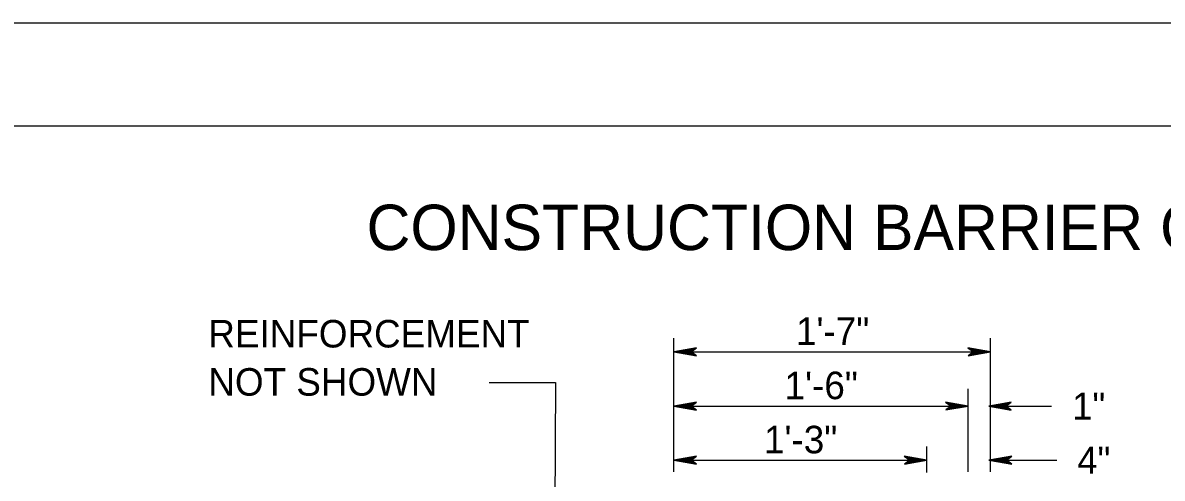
# Model space of a CAD drawing. Extents: x 499866 to 500993, y 499985 to 500645.
# Drawn here: x 500238.9 to 500404.4, y 500578.8 to 500645 of the extents above; entities that cross this region are included whole.
import ezdxf

# ---------------------------------------------------------------- set-up
doc = ezdxf.new("R2010")
doc.units = 0
for name, color, linetype in [('1', 7, 'Continuous'), ('24', 7, 'Continuous'), ('41', 7, 'Continuous'), ('5', 7, 'Continuous')]:
    doc.layers.add(name, color=color, linetype=linetype)

msp = doc.modelspace()

# ---------------------------------------------------------------- linework, layer by layer
at = {"layer": '1'}
for p, q in [((499944.83, 500645), (500993, 500645)), ((500990, 500630), (500000, 500630))]:
    msp.add_line(p, q, dxfattribs=at)
at = {"layer": '24'}
for points in [[(500333.48, 500597.19), (500336.76, 500596.61), (500335.97, 500597.19), (500336.74, 500597.76), (500333.48, 500597.19), (500333.7, 500597.19), (500336.66, 500596.65), (500335.91, 500597.19), (500336.61, 500597.71), (500333.82, 500597.2), (500333.93, 500597.19), (500336.47, 500596.74), (500335.9, 500597.19), (500336.48, 500597.64), (500333.98, 500597.19), (500334.08, 500597.2), (500336.3, 500596.8), (500335.87, 500597.19), (500336.31, 500597.59), (500334.4, 500597.2), (500334.59, 500597.2), (500336.14, 500596.88), (500335.84, 500597.18), (500336.16, 500597.5), (500334.62, 500597.19), (500334.79, 500597.18), (500335.96, 500596.98), (500335.74, 500597.2), (500335.98, 500597.43), (500334.95, 500597.19), (500335.12, 500597.17), (500335.82, 500597.04), (500335.7, 500597.19), (500335.9, 500597.37), (500335.2, 500597.19), (500335.66, 500597.08), (500335.6, 500597.2), (500335.8, 500597.33), (500335.32, 500597.2), (500335.62, 500597.13), (500335.49, 500597.23), (500335.64, 500597.29), (500335.49, 500597.19), (500335.57, 500597.18)], [(500379.45, 500597.19), (500376.17, 500597.77), (500376.96, 500597.19), (500376.19, 500596.62), (500379.45, 500597.19), (500379.23, 500597.18), (500376.26, 500597.72), (500377.02, 500597.18), (500376.32, 500596.66), (500379.11, 500597.17), (500379, 500597.19), (500376.46, 500597.64), (500377.03, 500597.18), (500376.45, 500596.74), (500378.95, 500597.19), (500378.84, 500597.17), (500376.62, 500597.57), (500377.06, 500597.19), (500376.62, 500596.79), (500378.53, 500597.17), (500378.34, 500597.17), (500376.79, 500597.49), (500377.09, 500597.2), (500376.77, 500596.87), (500378.31, 500597.19), (500378.14, 500597.2), (500376.97, 500597.4), (500377.19, 500597.17), (500376.95, 500596.95), (500377.98, 500597.19), (500377.81, 500597.2), (500377.11, 500597.34), (500377.22, 500597.18), (500377.03, 500597), (500377.73, 500597.19), (500377.27, 500597.3), (500377.33, 500597.17), (500377.13, 500597.04), (500377.61, 500597.17), (500377.31, 500597.25), (500377.44, 500597.15), (500377.29, 500597.09), (500377.43, 500597.18), (500377.36, 500597.2)], [(500333.48, 500589.31), (500336.76, 500588.73), (500335.97, 500589.31), (500336.74, 500589.88), (500333.48, 500589.31), (500333.7, 500589.32), (500336.66, 500588.78), (500335.91, 500589.32), (500336.61, 500589.84), (500333.82, 500589.33), (500333.93, 500589.31), (500336.47, 500588.86), (500335.9, 500589.32), (500336.48, 500589.76), (500333.98, 500589.31), (500334.08, 500589.33), (500336.3, 500588.93), (500335.87, 500589.31), (500336.31, 500589.71), (500334.4, 500589.33), (500334.59, 500589.33), (500336.14, 500589.01), (500335.84, 500589.3), (500336.16, 500589.63), (500334.62, 500589.31), (500334.79, 500589.3), (500335.96, 500589.1), (500335.74, 500589.33), (500335.98, 500589.55), (500334.95, 500589.31), (500335.12, 500589.3), (500335.82, 500589.16), (500335.7, 500589.32), (500335.9, 500589.49), (500335.2, 500589.31), (500335.66, 500589.2), (500335.6, 500589.33), (500335.8, 500589.45), (500335.32, 500589.33), (500335.62, 500589.25), (500335.49, 500589.35), (500335.64, 500589.41), (500335.49, 500589.32), (500335.57, 500589.3)], [(500376.2, 500589.31), (500372.93, 500589.89), (500373.71, 500589.31), (500372.94, 500588.74), (500376.2, 500589.31), (500375.98, 500589.31), (500373.02, 500589.85), (500373.77, 500589.31), (500373.08, 500588.79), (500375.87, 500589.3), (500375.76, 500589.31), (500373.22, 500589.76), (500373.79, 500589.31), (500373.2, 500588.86), (500375.71, 500589.31), (500375.6, 500589.3), (500373.38, 500589.7), (500373.81, 500589.31), (500373.37, 500588.91), (500375.28, 500589.3), (500375.1, 500589.3), (500373.54, 500589.61), (500373.85, 500589.32), (500373.52, 500589), (500375.07, 500589.31), (500374.89, 500589.32), (500373.72, 500589.52), (500373.95, 500589.3), (500373.7, 500589.07), (500374.73, 500589.31), (500374.57, 500589.33), (500373.86, 500589.46), (500373.98, 500589.31), (500373.79, 500589.13), (500374.48, 500589.31), (500374.02, 500589.42), (500374.09, 500589.3), (500373.89, 500589.17), (500374.36, 500589.3), (500374.06, 500589.37), (500374.19, 500589.27), (500374.05, 500589.21), (500374.19, 500589.31), (500374.11, 500589.32)], [(500379.2, 500589.31), (500382.47, 500588.73), (500381.69, 500589.31), (500382.46, 500589.88), (500379.2, 500589.31), (500379.42, 500589.32), (500382.38, 500588.78), (500381.63, 500589.32), (500382.32, 500589.84), (500379.53, 500589.33), (500379.64, 500589.31), (500382.18, 500588.86), (500381.61, 500589.32), (500382.2, 500589.76), (500379.69, 500589.31), (500379.8, 500589.33), (500382.02, 500588.93), (500381.59, 500589.31), (500382.03, 500589.71), (500380.12, 500589.33), (500380.3, 500589.33), (500381.86, 500589.01), (500381.56, 500589.3), (500381.88, 500589.63), (500380.34, 500589.31), (500380.51, 500589.3), (500381.68, 500589.1), (500381.45, 500589.33), (500381.7, 500589.55), (500380.67, 500589.31), (500380.84, 500589.3), (500381.54, 500589.16), (500381.42, 500589.32), (500381.61, 500589.49), (500380.92, 500589.31), (500381.38, 500589.2), (500381.31, 500589.33), (500381.51, 500589.45), (500381.04, 500589.33), (500381.34, 500589.25), (500381.21, 500589.35), (500381.36, 500589.41), (500381.21, 500589.32), (500381.29, 500589.3)], [(500333.48, 500581.44), (500336.76, 500580.86), (500335.97, 500581.44), (500336.74, 500582.01), (500333.48, 500581.44), (500333.7, 500581.44), (500336.66, 500580.9), (500335.91, 500581.45), (500336.61, 500581.96), (500333.82, 500581.45), (500333.93, 500581.44), (500336.47, 500580.99), (500335.9, 500581.45), (500336.48, 500581.89), (500333.98, 500581.44), (500334.08, 500581.45), (500336.3, 500581.05), (500335.87, 500581.44), (500336.31, 500581.84), (500334.4, 500581.46), (500334.59, 500581.45), (500336.14, 500581.14), (500335.84, 500581.43), (500336.16, 500581.75), (500334.62, 500581.44), (500334.79, 500581.43), (500335.96, 500581.23), (500335.74, 500581.46), (500335.98, 500581.68), (500334.95, 500581.44), (500335.12, 500581.42), (500335.82, 500581.29), (500335.7, 500581.45), (500335.9, 500581.62), (500335.2, 500581.44), (500335.66, 500581.33), (500335.6, 500581.45), (500335.8, 500581.58), (500335.32, 500581.46), (500335.62, 500581.38), (500335.49, 500581.48), (500335.64, 500581.54), (500335.49, 500581.45), (500335.57, 500581.43)], [(500370.21, 500581.44), (500366.93, 500582.02), (500367.71, 500581.44), (500366.95, 500580.87), (500370.21, 500581.44), (500369.99, 500581.43), (500367.02, 500581.97), (500367.78, 500581.43), (500367.08, 500580.91), (500369.87, 500581.42), (500369.76, 500581.44), (500367.22, 500581.89), (500367.79, 500581.43), (500367.21, 500580.99), (500369.71, 500581.44), (500369.6, 500581.42), (500367.38, 500581.82), (500367.82, 500581.44), (500367.38, 500581.04), (500369.29, 500581.42), (500369.1, 500581.42), (500367.55, 500581.74), (500367.85, 500581.45), (500367.53, 500581.12), (500369.07, 500581.44), (500368.9, 500581.45), (500367.73, 500581.65), (500367.95, 500581.42), (500367.71, 500581.2), (500368.73, 500581.44), (500368.57, 500581.46), (500367.87, 500581.59), (500367.98, 500581.43), (500367.79, 500581.26), (500368.48, 500581.44), (500368.03, 500581.55), (500368.09, 500581.42), (500367.89, 500581.3), (500368.37, 500581.42), (500368.07, 500581.5), (500368.19, 500581.4), (500368.05, 500581.34), (500368.19, 500581.43), (500368.12, 500581.45)], [(500379.2, 500581.44), (500382.55, 500580.85), (500381.75, 500581.44), (500382.53, 500582.02), (500379.2, 500581.44), (500379.42, 500581.44), (500382.46, 500580.89), (500381.69, 500581.45), (500382.4, 500581.98), (500379.54, 500581.46), (500379.65, 500581.44), (500382.25, 500580.98), (500381.67, 500581.45), (500382.27, 500581.9), (500379.71, 500581.44), (500379.82, 500581.46), (500382.09, 500581.04), (500381.65, 500581.44), (500382.1, 500581.85), (500380.14, 500581.46), (500380.33, 500581.46), (500381.92, 500581.13), (500381.61, 500581.43), (500381.94, 500581.76), (500380.36, 500581.44), (500380.54, 500581.43), (500381.74, 500581.22), (500381.51, 500581.46), (500381.76, 500581.68), (500380.71, 500581.44), (500380.87, 500581.42), (500381.59, 500581.28), (500381.47, 500581.45), (500381.67, 500581.62), (500380.96, 500581.44), (500381.43, 500581.33), (500381.36, 500581.46), (500381.57, 500581.58), (500381.08, 500581.46), (500381.39, 500581.38), (500381.26, 500581.48), (500381.41, 500581.54), (500381.26, 500581.45), (500381.34, 500581.43)]]:
    msp.add_lwpolyline(points, dxfattribs=at)
at = {"layer": '41'}
msp.add_lwpolyline([(499944.83, 500645), (500993, 500645), (500993, 499985), (499944.83, 499985)], close=True, dxfattribs=at)
at = {"layer": '5'}
for p, q in [((500333.48, 500579.77), (500333.48, 500599.16)), ((500379.45, 500579.77), (500379.45, 500599.16)), ((500333.48, 500597.19), (500379.45, 500597.19)), ((500376.2, 500579.77), (500376.2, 500591.8)), ((500333.48, 500589.31), (500376.2, 500589.31)), ((500379.2, 500589.31), (500388.32, 500589.31)), ((500370.21, 500579.64), (500370.21, 500583.44)), ((500333.48, 500581.44), (500370.21, 500581.44)), ((500379.2, 500581.44), (500389.06, 500581.44))]:
    msp.add_line(p, q, dxfattribs=at)
msp.add_lwpolyline([(500306.65, 500592.74), (500316.29, 500592.74), (500316.18, 500574.58)], dxfattribs=at)

# ---------------------------------------------------------------- texts
for s, height, p in [('CONSTRUCTION BARRIER CURB CONNECTION DETAILS', 6.6001, (500288.83, 500611.97)), ('REINFORCEMENT', 4, (500265.86, 500597.82)), ('1\'-7"', 4, (500351.2, 500598.19)), ('NOT SHOWN', 4, (500265.86, 500590.82)), ('1\'-6"', 4, (500349.54, 500590.31)), ('1"', 3.937, (500391.32, 500587.34)), ('1\'-3"', 4, (500346.55, 500582.44)), ('4"', 3.937, (500392.06, 500579.47))]:
    msp.add_text(s, height=height, dxfattribs=at).set_placement(p)

doc.saveas('drawing.dxf')
